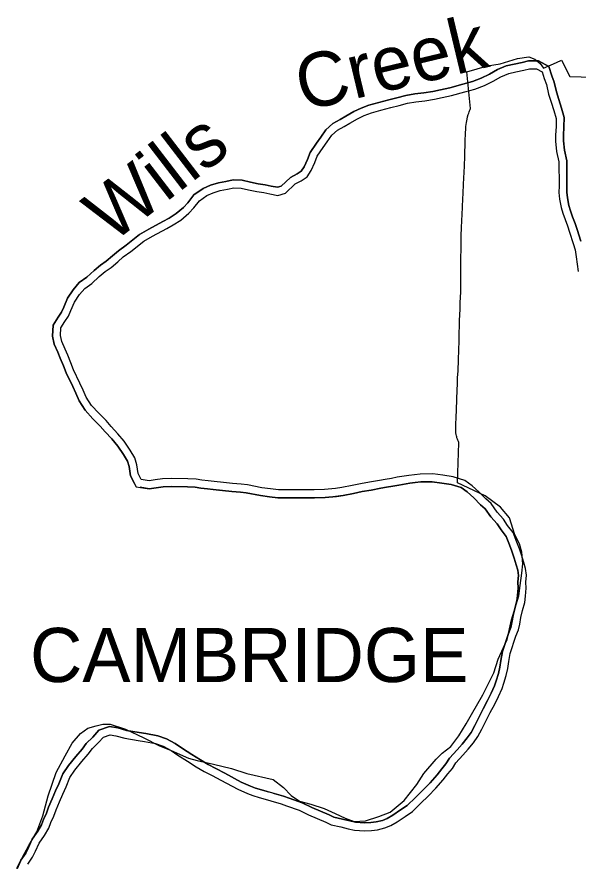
# Model space of a CAD drawing. Extents: x -29.6 to 34, y 0 to 22.
# Drawn here: x 2.653 to 3.803, y 16.793 to 18.526 of the extents above; entities that cross this region are included whole.
import ezdxf

# ---------------------------------------------------------------- set-up
doc = ezdxf.new("R2010")
doc.units = 0
for name, color, linetype in [('GM_X_Corporation', 7, 'Continuous'), ('GM_X_Corporation_Text', 7, 'Continuous'), ('GM_X_Major_River', 7, 'Continuous'), ('GM_X_Major_River_Text', 7, 'Continuous'), ('GM_X_Minor_River', 7, 'Continuous')]:
    doc.layers.add(name, color=color, linetype=linetype)

msp = doc.modelspace()

# ---------------------------------------------------------------- linework, layer by layer
at = {"layer": 'GM_X_Corporation'}
msp.add_lwpolyline([(2.6541, 16.7805), (2.6636, 16.8019), (2.6773, 16.8277), (2.6936, 16.8558), (2.7061, 16.8885), (2.7168, 16.9293), (2.7332, 16.9769), (2.7516, 17.0113), (2.7662, 17.0375), (2.783, 17.0568), (2.7984, 17.0684), (2.8156, 17.0727), (2.8294, 17.0765), (2.8444, 17.0761), (2.8753, 17.0658), (2.9131, 17.0482), (2.9436, 17.0327), (2.9694, 17.022), (3.0046, 17.0067), (3.0222, 17.0017), (3.0562, 16.9941), (3.0927, 16.9853), (3.1242, 16.9752), (3.1784, 16.9627), (3.1998, 16.9463), (3.2149, 16.9299), (3.2325, 16.9186), (3.2552, 16.9123), (3.2829, 16.9035), (3.3056, 16.8934), (3.3257, 16.8833), (3.3446, 16.877), (3.3673, 16.8783), (3.395, 16.8871), (3.418, 16.8956), (3.4466, 16.9198), (3.4731, 16.9526), (3.487, 16.9752), (3.5121, 17.0042), (3.5247, 17.0168), (3.5424, 17.0306), (3.5587, 17.0521), (3.5738, 17.0772), (3.5852, 17.0961), (3.6078, 17.1364), (3.6305, 17.1818), (3.6393, 17.2095), (3.6582, 17.2498), (3.667, 17.2901), (3.6821, 17.3395), (3.6847, 17.3603), (3.6878, 17.3855), (3.6903, 17.405), (3.6878, 17.4289), (3.6834, 17.4459), (3.674, 17.4642), (3.6625, 17.4993), (3.6443, 17.5213), (3.6126, 17.5444), (3.5565, 17.5712), (3.5592, 17.6532), (3.5588, 17.6539), (3.5579, 17.6558), (3.5569, 17.6583), (3.556, 17.6604), (3.5551, 17.663), (3.5545, 17.6651), (3.5539, 17.6674), (3.5534, 17.6698), (3.5529, 17.6737), (3.5527, 17.6766), (3.5525, 17.6802), (3.5525, 17.6844), (3.5526, 17.6891), (3.5529, 17.6948), (3.5532, 17.7017), (3.5535, 17.7094), (3.5539, 17.7168), (3.5542, 17.7268), (3.5546, 17.7354), (3.5549, 17.7441), (3.5561, 17.7754), (3.5563, 17.7811), (3.5565, 17.7864), (3.5572, 17.8007), (3.558, 17.8233), (3.5586, 17.8436), (3.5593, 17.8613), (3.5599, 17.8776), (3.5602, 17.8928), (3.5604, 17.9041), (3.5609, 17.9155), (3.5613, 17.9268), (3.5618, 17.9407), (3.5627, 17.9622), (3.563, 17.9728), (3.5631, 17.9824), (3.563, 17.9934), (3.5631, 18.0117), (3.5632, 18.034), (3.5634, 18.049), (3.5635, 18.0658), (3.5637, 18.0728), (3.5638, 18.079), (3.5645, 18.0928), (3.5652, 18.1094), (3.5656, 18.1204), (3.5673, 18.1536), (3.5678, 18.1645), (3.5687, 18.1834), (3.5705, 18.2204), (3.5712, 18.2407), (3.5722, 18.2713), (3.5727, 18.2877), (3.5731, 18.2966), (3.5735, 18.3016), (3.574, 18.3058), (3.5745, 18.3095), (3.5752, 18.3135), (3.5758, 18.3167), (3.5769, 18.3215), (3.5782, 18.3262), (3.5791, 18.3287), (3.5799, 18.3313), (3.5809, 18.3337), (3.5819, 18.3362), (3.5829, 18.3382), (3.5752, 18.4134), (3.6177, 18.4259), (3.6434, 18.4298), (3.679, 18.4407), (3.7027, 18.4446), (3.7146, 18.4397), (3.7254, 18.4306), (3.7328, 18.421), (3.7589, 18.4328), (3.7696, 18.4376), (3.7866, 18.404), (4.1851, 18.3923)], dxfattribs=at)
at = {"layer": 'GM_X_Major_River'}
for points in [[(2.8936, 17.5701), (2.8855, 17.5851), (2.8829, 17.6047), (2.8798, 17.6155), (2.8712, 17.6293), (2.8598, 17.6464), (2.8477, 17.6609), (2.8339, 17.6758), (2.8239, 17.6875), (2.8089, 17.7023), (2.7929, 17.72), (2.7808, 17.7389), (2.7736, 17.7546), (2.7673, 17.7687), (2.7542, 17.7963), (2.7482, 17.8109), (2.7418, 17.8265), (2.737, 17.8386), (2.7293, 17.8553), (2.7256, 17.8718), (2.7273, 17.8941), (2.7374, 17.9107), (2.7443, 17.921), (2.7489, 17.9313), (2.7568, 17.9493), (2.7682, 17.9669), (2.7808, 17.9819), (2.7962, 17.9924), (2.811, 18.0061), (2.8242, 18.0171), (2.8361, 18.0257), (2.8491, 18.0363), (2.8609, 18.0469), (2.8767, 18.0585), (2.9042, 18.08), (2.9231, 18.0911), (2.9523, 18.1065), (2.965, 18.1138), (2.9796, 18.1229), (2.9942, 18.1353), (3.0032, 18.1452), (3.0157, 18.1615), (3.0346, 18.1746), (3.0497, 18.181), (3.066, 18.1861), (3.0813, 18.189), (3.0963, 18.1921), (3.1146, 18.1917), (3.1315, 18.1875), (3.1476, 18.1842), (3.1618, 18.1821), (3.1745, 18.1794), (3.1869, 18.1772), (3.195, 18.1795), (3.2141, 18.1973), (3.2275, 18.2042), (3.236, 18.2099), (3.2421, 18.2189), (3.2484, 18.2338), (3.2542, 18.2482), (3.2672, 18.2677), (3.276, 18.2799), (3.2863, 18.2948), (3.3009, 18.3075), (3.3155, 18.3159), (3.3274, 18.3227), (3.3434, 18.332), (3.3587, 18.3393), (3.3746, 18.3453), (3.395, 18.351), (3.4154, 18.356), (3.432, 18.3606), (3.4501, 18.3653), (3.4684, 18.3683), (3.4872, 18.3707), (3.5058, 18.3734), (3.5212, 18.3769), (3.5402, 18.381), (3.5668, 18.3886), (3.587, 18.3939), (3.6049, 18.4006), (3.6218, 18.409), (3.6381, 18.4183), (3.6562, 18.426), (3.6725, 18.4296), (3.6884, 18.4327), (3.7017, 18.4364), (3.722, 18.4359), (3.7434, 18.4249), (3.7494, 18.4054), (3.7541, 18.3925), (3.7588, 18.3723), (3.764, 18.3566), (3.7695, 18.3393), (3.7748, 18.3198), (3.7744, 18.3008), (3.7737, 18.2834), (3.7733, 18.2723), (3.7755, 18.2529), (3.7802, 18.2313), (3.7806, 18.1802)], [(3.7806, 18.18), (3.7802, 18.2313), (3.7755, 18.2529), (3.7733, 18.2723), (3.7737, 18.2834), (3.7744, 18.3008), (3.7748, 18.3198), (3.7695, 18.3393), (3.764, 18.3566), (3.7588, 18.3723), (3.7541, 18.3925), (3.7494, 18.4054), (3.7434, 18.4249), (3.722, 18.4359), (3.7017, 18.4364), (3.6884, 18.4327), (3.6725, 18.4296), (3.6562, 18.426), (3.6381, 18.4183), (3.6218, 18.409), (3.6049, 18.4006), (3.587, 18.3939), (3.5668, 18.3886), (3.5402, 18.381), (3.5212, 18.3769), (3.5058, 18.3734), (3.4872, 18.3707), (3.4684, 18.3683), (3.4501, 18.3653), (3.432, 18.3606), (3.4154, 18.356), (3.395, 18.351), (3.3746, 18.3453), (3.3587, 18.3393), (3.3434, 18.332), (3.3274, 18.3227), (3.3155, 18.3159), (3.3009, 18.3075), (3.2863, 18.2948), (3.276, 18.2799), (3.2672, 18.2677), (3.2542, 18.2482), (3.2484, 18.2338), (3.2421, 18.2189), (3.236, 18.2099), (3.2275, 18.2042), (3.2141, 18.1973), (3.195, 18.1795), (3.1869, 18.1772), (3.1745, 18.1794), (3.1618, 18.1821), (3.1476, 18.1842), (3.1315, 18.1875), (3.1146, 18.1917), (3.0963, 18.1921), (3.0813, 18.189), (3.066, 18.1861), (3.0497, 18.181), (3.0346, 18.1746), (3.0157, 18.1615), (3.0032, 18.1452), (2.9942, 18.1353), (2.9796, 18.1229), (2.965, 18.1138), (2.9523, 18.1065), (2.9231, 18.0911), (2.9042, 18.08), (2.8767, 18.0585), (2.8609, 18.0469), (2.8491, 18.0363), (2.8361, 18.0257), (2.8242, 18.0171), (2.811, 18.0061), (2.7962, 17.9924), (2.7808, 17.9819), (2.7682, 17.9669), (2.7568, 17.9493), (2.7489, 17.9313), (2.7443, 17.921), (2.7374, 17.9107), (2.7273, 17.8941), (2.7256, 17.8718), (2.7293, 17.8553), (2.737, 17.8386), (2.7418, 17.8265), (2.7482, 17.8109), (2.7542, 17.7963), (2.7673, 17.7687), (2.7736, 17.7546), (2.7808, 17.7389), (2.7929, 17.72), (2.8089, 17.7023), (2.8239, 17.6875), (2.8339, 17.6758), (2.8477, 17.6609), (2.8598, 17.6464), (2.8712, 17.6293), (2.8798, 17.6155), (2.8829, 17.6047), (2.8855, 17.5851), (2.8975, 17.563)], [(2.908, 17.5779), (2.9012, 17.5903), (2.8989, 17.608), (2.8948, 17.6222), (2.885, 17.6381), (2.8729, 17.6562), (2.8599, 17.6717), (2.8461, 17.6867), (2.8358, 17.6986), (2.8207, 17.7136), (2.8059, 17.7299), (2.7952, 17.7467), (2.7885, 17.7613), (2.7822, 17.7755), (2.7691, 17.803), (2.7633, 17.8171), (2.757, 17.8326), (2.752, 17.845), (2.7448, 17.8605), (2.7421, 17.8729), (2.7433, 17.8889), (2.7512, 17.9019), (2.7586, 17.913), (2.7638, 17.9246), (2.7713, 17.9416), (2.7813, 17.9572), (2.7919, 17.9697), (2.8064, 17.9796), (2.8218, 17.9939), (2.8342, 18.0042), (2.8461, 18.0127), (2.8597, 18.0239), (2.8711, 18.0342), (2.8866, 18.0454), (2.9134, 18.0665), (2.9311, 18.0768), (2.9602, 18.0922), (2.9734, 18.0998), (2.9893, 18.1097), (3.0056, 18.1236), (3.0157, 18.1347), (3.0271, 18.1495), (3.0425, 18.1603), (3.0553, 18.1657), (3.0699, 18.1702), (3.0845, 18.173), (3.0978, 18.1758), (3.1124, 18.1754), (3.1279, 18.1715), (3.1448, 18.1681), (3.159, 18.166), (3.1714, 18.1634), (3.1878, 18.1604), (3.2033, 18.165), (3.2235, 18.1838), (3.2359, 18.1901), (3.2478, 18.1982), (3.2565, 18.2111), (3.2635, 18.2276), (3.2687, 18.2405), (3.2806, 18.2584), (3.2893, 18.2704), (3.2985, 18.2838), (3.3104, 18.2941), (3.3237, 18.3018), (3.3356, 18.3085), (3.351, 18.3175), (3.3651, 18.3243), (3.3797, 18.3297), (3.3991, 18.3352), (3.4195, 18.3402), (3.4363, 18.3448), (3.4535, 18.3494), (3.4708, 18.3521), (3.4894, 18.3545), (3.5088, 18.3573), (3.5247, 18.361), (3.5442, 18.3651), (3.5712, 18.3729), (3.5919, 18.3783), (3.6114, 18.3856), (3.6295, 18.3946), (3.6453, 18.4036), (3.6612, 18.4104), (3.6758, 18.4136), (3.6922, 18.4168), (3.7037, 18.42), (3.7179, 18.4197), (3.7299, 18.4135), (3.7339, 18.4002), (3.7385, 18.3878), (3.743, 18.3679), (3.7485, 18.3515), (3.7539, 18.3346), (3.7584, 18.3178), (3.7581, 18.3014), (3.7574, 18.284), (3.757, 18.2716), (3.7594, 18.2503), (3.7639, 18.2294), (3.7643, 18.1801)], [(3.7643, 18.1801), (3.7639, 18.1664), (3.7654, 18.1526), (3.7686, 18.1357), (3.7722, 18.1238), (3.7767, 18.1109), (3.7817, 18.0976), (3.7858, 18.0852), (3.7935, 18.0617), (3.7971, 18.0484), (3.7994, 18.0342), (3.8017, 18.0196), (3.8036, 18.0041)], [(3.8091, 18.0664), (3.8013, 18.0903), (3.7971, 18.103), (3.7921, 18.1165), (3.7877, 18.1288), (3.7845, 18.1396), (3.7815, 18.155), (3.7803, 18.167), (3.7806, 18.18)], [(3.7806, 18.1797), (3.7803, 18.167), (3.7815, 18.155), (3.7845, 18.1396), (3.7877, 18.1288), (3.7921, 18.1165), (3.7971, 18.103), (3.8013, 18.0903), (3.8091, 18.0664)], [(3.1733, 16.9194), (3.1946, 16.9129), (3.2057, 16.909), (3.2315, 16.8999), (3.251, 16.8907), (3.2688, 16.8828), (3.2861, 16.8754), (3.2972, 16.8701), (3.3167, 16.8658), (3.3318, 16.8619), (3.3447, 16.8589), (3.3655, 16.8573), (3.3801, 16.8583), (3.3921, 16.8597), (3.4071, 16.8634), (3.4195, 16.8683), (3.4322, 16.876), (3.4486, 16.8868), (3.4636, 16.8971), (3.4811, 16.9145), (3.4957, 16.9284), (3.5119, 16.9449), (3.5269, 16.9619), (3.5365, 16.9744), (3.5458, 16.9856), (3.5528, 16.9967), (3.5673, 17.0124), (3.5783, 17.0249), (3.5893, 17.0383), (3.598, 17.0508), (3.6059, 17.066), (3.6142, 17.0824), (3.6234, 17.1003), (3.6326, 17.1172), (3.64, 17.1328), (3.6474, 17.1493), (3.6509, 17.1604), (3.6556, 17.176), (3.6591, 17.1902), (3.6612, 17.2045), (3.6642, 17.2214), (3.6759, 17.2565), (3.6811, 17.2694), (3.6837, 17.2815), (3.6863, 17.2952), (3.6897, 17.3095), (3.694, 17.3259), (3.6957, 17.3384), (3.6969, 17.3548), (3.6964, 17.3677), (3.6976, 17.3815), (3.6958, 17.3957), (3.6921, 17.4076), (3.6881, 17.4214), (3.6831, 17.436), (3.6781, 17.4497), (3.67, 17.4692), (3.6588, 17.4838), (3.6508, 17.4966), (3.6374, 17.5112), (3.6253, 17.5289), (3.6142, 17.5381), (3.6008, 17.5518), (3.5861, 17.565), (3.5714, 17.576), (3.547, 17.5834), (3.5262, 17.5868), (3.5053, 17.5893), (3.4796, 17.5891), (3.4677, 17.5877), (3.4562, 17.5863), (3.4327, 17.5825), (3.4208, 17.5802), (3.408, 17.5779), (3.3965, 17.5761), (3.3761, 17.5724), (3.3575, 17.5691), (3.3399, 17.5654), (3.3191, 17.5613), (3.3062, 17.5594), (3.2837, 17.5575), (3.2624, 17.5564), (3.2412, 17.5567), (3.2009, 17.5564), (3.1889, 17.5568), (3.1725, 17.5585), (3.1548, 17.561), (3.1255, 17.567), (3.1126, 17.5683), (3.0949, 17.5695), (3.0763, 17.5715), (3.0572, 17.5736), (3.0453, 17.5749), (3.032, 17.5766), (3.0205, 17.5782), (3.0032, 17.5795), (2.9695, 17.5797), (2.9514, 17.5791), (2.9363, 17.5772), (2.9244, 17.5753), (2.908, 17.5779)], [(2.8975, 17.563), (2.9244, 17.5588), (2.9386, 17.561), (2.9526, 17.5628), (2.9697, 17.5633), (3.0026, 17.5631), (3.0187, 17.562), (3.0298, 17.5604), (3.0434, 17.5587), (3.0555, 17.5574), (3.0745, 17.5553), (3.0935, 17.5532), (3.1113, 17.552), (3.1231, 17.5508), (3.152, 17.5449), (3.1705, 17.5423), (3.1878, 17.5405), (3.2007, 17.5401), (3.2411, 17.5404), (3.2627, 17.5401), (3.2848, 17.5412), (3.3081, 17.5432), (3.3218, 17.5452), (3.3431, 17.5494), (3.3606, 17.5531), (3.379, 17.5563), (3.3992, 17.56), (3.4107, 17.5618), (3.4238, 17.5642), (3.4356, 17.5665), (3.4585, 17.5701), (3.4697, 17.5715), (3.4807, 17.5728), (3.5044, 17.573), (3.5239, 17.5706), (3.5433, 17.5674), (3.5639, 17.5612), (3.5757, 17.5524), (3.5895, 17.54), (3.6031, 17.5261), (3.6131, 17.5178), (3.6246, 17.501), (3.6378, 17.4867), (3.6454, 17.4745), (3.6558, 17.461), (3.6629, 17.4438), (3.6677, 17.4306), (3.6725, 17.4164), (3.6765, 17.403), (3.6798, 17.3922), (3.6812, 17.3811), (3.6801, 17.3681), (3.6806, 17.3551), (3.6795, 17.3401), (3.678, 17.3291), (3.6739, 17.3135), (3.6703, 17.2987), (3.6677, 17.2847), (3.6655, 17.2743), (3.6606, 17.2622), (3.6483, 17.2254), (3.6451, 17.2071), (3.643, 17.1934), (3.6399, 17.1803), (3.6353, 17.1652), (3.6321, 17.1551), (3.6252, 17.1397), (3.618, 17.1246), (3.6089, 17.1079), (3.5997, 17.0899), (3.5914, 17.0734), (3.584, 17.0593), (3.5762, 17.0482), (3.5658, 17.0355), (3.5552, 17.0233), (3.5398, 17.0067), (3.5325, 16.9952), (3.5238, 16.9846), (3.5143, 16.9723), (3.5, 16.9561), (3.4842, 16.94), (3.4698, 16.9262), (3.4531, 16.9097), (3.4394, 16.9003), (3.4236, 16.8898), (3.4122, 16.883), (3.4021, 16.8789), (3.3892, 16.8758), (3.3786, 16.8745), (3.3656, 16.8737), (3.3472, 16.8751), (3.3357, 16.8778), (3.3205, 16.8817), (3.3025, 16.8857), (3.2928, 16.8903), (3.2753, 16.8978), (3.2578, 16.9055), (3.2377, 16.915), (3.2112, 16.9244), (3.1997, 16.9284), (3.1778, 16.9351)], [(3.1781, 16.935), (3.1997, 16.9284), (3.2112, 16.9244), (3.2377, 16.915), (3.2578, 16.9055), (3.2753, 16.8978), (3.2928, 16.8903), (3.3025, 16.8857), (3.3205, 16.8817), (3.3357, 16.8778), (3.3472, 16.8751), (3.3656, 16.8737), (3.3786, 16.8745), (3.3892, 16.8758), (3.4021, 16.8789), (3.4122, 16.883), (3.4236, 16.8898), (3.4394, 16.9003), (3.4531, 16.9097), (3.4698, 16.9262), (3.4842, 16.94), (3.5, 16.9561), (3.5143, 16.9723), (3.5238, 16.9846), (3.5325, 16.9952), (3.5398, 17.0067), (3.5552, 17.0233), (3.5658, 17.0355), (3.5762, 17.0482), (3.584, 17.0593), (3.5914, 17.0734), (3.5997, 17.0899), (3.6089, 17.1079), (3.618, 17.1246), (3.6252, 17.1397), (3.6321, 17.1551), (3.6353, 17.1652), (3.6399, 17.1803), (3.643, 17.1934), (3.6451, 17.2071), (3.6483, 17.2254), (3.6606, 17.2622), (3.6655, 17.2743), (3.6677, 17.2847), (3.6703, 17.2987), (3.6739, 17.3135), (3.678, 17.3291), (3.6795, 17.3401), (3.6806, 17.3551), (3.6801, 17.3681), (3.6812, 17.3811), (3.6798, 17.3922), (3.6765, 17.403), (3.6725, 17.4164), (3.6677, 17.4306), (3.6629, 17.4438), (3.6558, 17.461), (3.6454, 17.4745), (3.6378, 17.4867), (3.6246, 17.501), (3.6131, 17.5178), (3.6031, 17.5261), (3.5895, 17.54), (3.5757, 17.5524), (3.5639, 17.5612), (3.5433, 17.5674), (3.5239, 17.5706), (3.5044, 17.573), (3.4807, 17.5728), (3.4697, 17.5715), (3.4585, 17.5701), (3.4356, 17.5665), (3.4238, 17.5642), (3.4107, 17.5618), (3.3992, 17.56), (3.379, 17.5563), (3.3606, 17.5531), (3.3431, 17.5494), (3.3218, 17.5452), (3.3081, 17.5432), (3.2848, 17.5412), (3.2627, 17.5401), (3.2411, 17.5404), (3.2007, 17.5401), (3.1878, 17.5405), (3.1705, 17.5423), (3.152, 17.5449), (3.1231, 17.5508), (3.1113, 17.552), (3.0935, 17.5532), (3.0745, 17.5553), (3.0555, 17.5574), (3.0434, 17.5587), (3.0298, 17.5604), (3.0187, 17.562), (3.0026, 17.5631), (2.9697, 17.5633), (2.9526, 17.5628), (2.9386, 17.561), (2.9244, 17.5588), (2.9055, 17.5618)], [(2.6529, 16.7802), (2.6608, 16.7975), (2.6711, 16.812), (2.6765, 16.8231), (2.6844, 16.8402), (2.6959, 16.857), (2.7036, 16.8699), (2.7076, 16.8811), (2.7133, 16.8936), (2.718, 16.9063), (2.7252, 16.9232), (2.7322, 16.9394), (2.7387, 16.9539), (2.7471, 16.9744), (2.7585, 16.9915), (2.7737, 17.0103), (2.7866, 17.0247), (2.7952, 17.0367), (2.8086, 17.0499), (2.8211, 17.0637), (2.8428, 17.0716), (2.8595, 17.0685), (2.8776, 17.0633), (2.9038, 17.0589), (2.9173, 17.0572), (2.9417, 17.0525), (2.9596, 17.046), (2.9774, 17.0363), (2.9921, 17.0263), (3.0114, 17.0141), (3.029, 17.0029), (3.0448, 16.9936), (3.061, 16.9854), (3.0789, 16.9757), (3.113, 16.9576), (3.1317, 16.9492), (3.1418, 16.9453), (3.1544, 16.9416), (3.1661, 16.9382), (3.1775, 16.9352)], [(3.1778, 16.9351), (3.1661, 16.9382), (3.1544, 16.9416), (3.1418, 16.9453), (3.1317, 16.9492), (3.113, 16.9576), (3.0789, 16.9757), (3.061, 16.9854), (3.0448, 16.9936), (3.029, 17.0029), (3.0114, 17.0141), (2.9921, 17.0263), (2.9774, 17.0363), (2.9596, 17.046), (2.9417, 17.0525), (2.9173, 17.0572), (2.9038, 17.0589), (2.8776, 17.0633), (2.8595, 17.0685), (2.8428, 17.0716), (2.8211, 17.0637), (2.8086, 17.0499), (2.7952, 17.0367), (2.7866, 17.0247), (2.7737, 17.0103), (2.7585, 16.9915), (2.7471, 16.9744), (2.7387, 16.9539), (2.7322, 16.9394), (2.7252, 16.9232), (2.718, 16.9063), (2.7133, 16.8936), (2.7076, 16.8811), (2.7036, 16.8699), (2.6959, 16.857), (2.6844, 16.8402), (2.6765, 16.8231), (2.6711, 16.812), (2.6608, 16.7975), (2.6529, 16.7802)], [(2.6751, 16.7893), (2.6851, 16.8036), (2.6913, 16.8161), (2.6987, 16.8321), (2.7096, 16.8482), (2.7184, 16.8629), (2.7228, 16.8749), (2.7284, 16.8874), (2.7332, 16.9003), (2.7402, 16.9168), (2.7472, 16.9328), (2.7537, 16.9475), (2.7615, 16.9667), (2.7716, 16.9818), (2.7861, 16.9997), (2.7993, 17.0145), (2.8076, 17.0261), (2.8204, 17.0386), (2.8305, 17.0498), (2.8442, 17.0547), (2.8557, 17.0526), (2.8739, 17.0474), (2.9014, 17.0427), (2.9147, 17.041), (2.9373, 17.0368), (2.9529, 17.0311), (2.9689, 17.0223), (2.9831, 17.0127), (3.0027, 17.0004), (3.0205, 16.9889), (3.0369, 16.9793), (3.0534, 16.971), (3.0712, 16.9613), (3.1058, 16.9429), (3.1254, 16.9342), (3.1365, 16.9298), (3.1498, 16.9259), (3.1618, 16.9225), (3.1733, 16.9194)]]:
    msp.add_lwpolyline(points, dxfattribs=at)
at = {"layer": 'GM_X_Minor_River'}
for p, q in [((3.0661, 17.5553), (3.0482, 17.5578)), ((3.3218, 17.5452), (3.3005, 17.5425))]:
    msp.add_line(p, q, dxfattribs=at)

# ---------------------------------------------------------------- texts
at = {"layer": 'GM_X_Corporation_Text'}
msp.add_text('CAMBRIDGE', height=0.11097, rotation=0, dxfattribs=at).set_placement((2.6799, 17.1626))
at = {"layer": 'GM_X_Major_River_Text'}
for s, height, rotation, p in [('Creek', 0.11096, 13.4421, (3.2395, 18.3325)), ('Wills', 0.11097, 37.5213, (2.847, 18.0602))]:
    msp.add_text(s, height=height, rotation=rotation, dxfattribs=at).set_placement(p)

doc.saveas('drawing.dxf')
